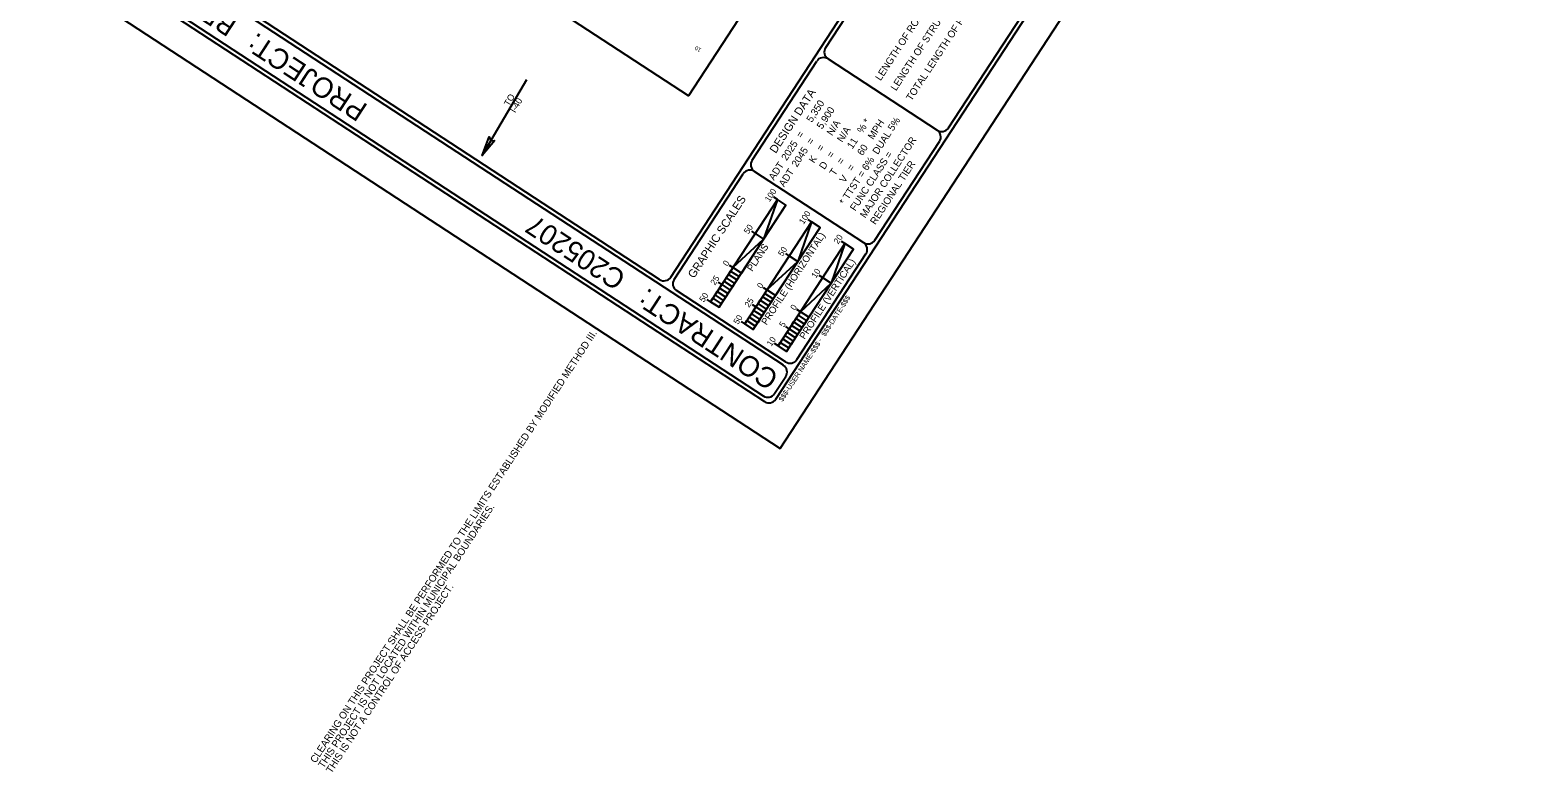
# Model space of a CAD drawing. Extents: x 1190029 to 2382315, y 163128 to 334830.
# Drawn here: x 2378613 to 2382315, y 329705 to 331527 of the extents above; entities that cross this region are included whole.
import ezdxf

# ---------------------------------------------------------------- set-up
doc = ezdxf.new("R2010")
doc.units = 0
for name, color, linetype in [('Exist Property Line', 7, 'Continuous'), ('Exist Utilities Telephone UG FO SUE LOS B Text', 7, 'Continuous'), ('Prop ROW Station Offsets', 7, 'Continuous'), ('Scratch_Level_4', 7, 'Continuous'), ('Sheet Block Title CELL', 7, 'Continuous'), ('Sheet_Plan_CELL', 7, 'Continuous'), ('z - Construction', 7, 'Continuous')]:
    doc.layers.add(name, color=color, linetype=linetype)

msp = doc.modelspace()

# ---------------------------------------------------------------- linework, layer by layer
at = {"layer": 'Exist Utilities Telephone UG FO SUE LOS B Text'}
for p, q in [((2380185.5, 330920.1), (2381876.3, 333506.5)), ((2380443.3, 330620.2), (2382199.8, 333307)), ((2380566, 331483.8), (2380981.8, 332119.9)), ((2380157.8, 330914.3), (2378801.9, 331800.8)), ((2380462, 330703.5), (2378796.4, 331792.4)), ((2378733.2, 331714.3), (2380415.6, 330614.4)), ((2378747.1, 331717.1), (2380412.8, 330628.2)), ((2380385.4, 331207.6), (2380544.1, 331450.3)), ((2380571.7, 331456.1), (2380839.6, 331281)), ((2380193.9, 330914.6), (2380363.5, 331174.1)), ((2380391.2, 331179.9), (2380659, 331004.8)), ((2380447.4, 331110.9), (2380283.2, 330859.8)), ((2380304.1, 330846.1), (2380468.3, 331097.2)), ((2380447.4, 331110.9), (2380439, 331116.4)), ((2380468.3, 331097.2), (2380447.4, 331110.9)), ((2380531.2, 331056.1), (2380522.9, 331061.6)), ((2380531.2, 331056.1), (2380367.1, 330805)), ((2380392.7, 331027.2), (2380384.3, 331032.7)), ((2380388, 330791.3), (2380552.2, 331042.4)), ((2380392.7, 331027.2), (2380413.6, 331013.5)), ((2380552.2, 331042.4), (2380531.2, 331056.1)), ((2380613.1, 331002.6), (2380448.9, 330751.5)), ((2380469.9, 330737.8), (2380634, 330988.9)), ((2380613.1, 331002.6), (2380604.7, 331008)), ((2380634, 330988.9), (2380613.1, 331002.6)), ((2380338, 330943.5), (2380329.6, 330949)), ((2380476.5, 330972.4), (2380468.2, 330977.9)), ((2380476.5, 330972.4), (2380497.4, 330958.7)), ((2380321.5, 330918.4), (2380342.4, 330904.7)), ((2380558.4, 330918.9), (2380550, 330924.3)), ((2380558.4, 330918.9), (2380579.3, 330905.2)), ((2380467.5, 330711.9), (2380199.7, 330887)), ((2380310.6, 330901.7), (2380302.2, 330907.1)), ((2380421.8, 330888.7), (2380413.4, 330894.2)), ((2380283.2, 330859.8), (2380274.9, 330865.3)), ((2380274.9, 330865.3), (2380274.9, 330865.3)), ((2380283.2, 330859.8), (2380304.1, 330846.1)), ((2380283.2, 330859.8), (2380283.2, 330859.8)), ((2380394.4, 330846.8), (2380386.1, 330852.3)), ((2380405.4, 330863.6), (2380426.3, 330849.9)), ((2380503.7, 330835.2), (2380495.3, 330840.6)), ((2380367.1, 330805), (2380358.7, 330810.5)), ((2380358.7, 330810.5), (2380358.7, 330810.5)), ((2380367.1, 330805), (2380388, 330791.3)), ((2380367.1, 330805), (2380367.1, 330805)), ((2380487.2, 330810.1), (2380508.2, 330796.4)), ((2380476.3, 330793.3), (2380467.9, 330798.8)), ((2380448.9, 330751.5), (2380440.6, 330756.9)), ((2380440.6, 330756.9), (2380440.6, 330756.9)), ((2380448.9, 330751.5), (2380469.9, 330737.8)), ((2380448.9, 330751.5), (2380448.9, 330751.5))]:
    msp.add_line(p, q, dxfattribs=at)
for points in [[(2380867.3, 331286.8), (2381283.2, 331922.9)], [(2380686.7, 331010.6), (2380845.4, 331253.3)], [(2380495.2, 330717.7), (2380664.8, 330977.1)], [(2380440.5, 330634), (2380467.8, 330675.8)]]:
    msp.add_lwpolyline(points, dxfattribs=at)
for points in [[(2380447.4, 331110.9), (2380413.6, 331013.5), (2380468.3, 331097.2)], [(2380531.2, 331056.1), (2380497.4, 330958.7), (2380552.2, 331042.4)], [(2380338, 330943.5), (2380413.6, 331013.5), (2380358.9, 330929.8)], [(2380613.1, 331002.6), (2380579.3, 330905.2), (2380634, 330988.9)], [(2380421.8, 330888.7), (2380497.4, 330958.7), (2380442.7, 330875)], [(2380316.1, 330910), (2380321.5, 330918.4), (2380342.4, 330904.7), (2380337, 330896.4)], [(2380327, 330926.8), (2380332.5, 330935.1), (2380353.4, 330921.5), (2380347.9, 330913.1)], [(2380294.2, 330876.6), (2380299.6, 330884.9), (2380320.6, 330871.2), (2380315.1, 330862.9)], [(2380305.1, 330893.3), (2380310.6, 330901.7), (2380331.5, 330888), (2380326, 330879.6)], [(2380410.8, 330872), (2380416.3, 330880.3), (2380437.3, 330866.6), (2380431.8, 330858.3)], [(2380503.7, 330835.2), (2380579.3, 330905.2), (2380524.6, 330821.5)], [(2380283.2, 330859.8), (2380288.7, 330868.2), (2380309.6, 330854.5), (2380304.1, 330846.1)], [(2380389, 330838.5), (2380394.4, 330846.8), (2380415.3, 330833.2), (2380409.9, 330824.8)], [(2380399.9, 330855.2), (2380405.4, 330863.6), (2380426.3, 330849.9), (2380420.8, 330841.5)], [(2380367.1, 330805), (2380372.5, 330813.4), (2380393.5, 330799.7), (2380388, 330791.3)], [(2380378, 330821.7), (2380383.5, 330830.1), (2380404.4, 330816.4), (2380399, 330808.1)], [(2380481.8, 330801.7), (2380487.2, 330810.1), (2380508.2, 330796.4), (2380502.7, 330788)], [(2380492.7, 330818.4), (2380498.2, 330826.8), (2380519.1, 330813.1), (2380513.6, 330804.7)], [(2380459.9, 330768.2), (2380465.4, 330776.6), (2380486.3, 330762.9), (2380480.8, 330754.5)], [(2380470.9, 330784.9), (2380476.3, 330793.3), (2380497.2, 330779.6), (2380491.8, 330771.3)], [(2380448.9, 330751.5), (2380454.4, 330759.8), (2380475.3, 330746.2), (2380469.9, 330737.8)]]:
    msp.add_lwpolyline(points, close=True, dxfattribs=at)
for centre, start, end in [((2380582.6, 331472.9), 146.8248, 236.8248), ((2380560.7, 331439.4), 56.8248, 146.8248), ((2380850.5, 331297.8), 236.8248, 326.8248), ((2380828.6, 331264.3), 326.8248, 56.8248), ((2380402.1, 331196.6), 146.8298, 236.8248), ((2380380.2, 331163.2), 56.8248, 146.8295), ((2380670, 331021.6), 236.8248, 326.8248), ((2380648.1, 330988.1), 326.8295, 56.8248), ((2380168.7, 330931.1), 236.8248, 326.8248), ((2380210.6, 330903.7), 146.8295, 236.8293), ((2380451, 330686.8), 326.8248, 56.8248), ((2380478.5, 330728.6), 236.8293, 326.8295), ((2380423.7, 330644.9), 236.8241, 326.8248), ((2380426.5, 330631.1), 236.8248, 326.8248)]:
    msp.add_arc(centre, 20, start, end, dxfattribs=at)
at = {"layer": 'Scratch_Level_4'}
msp.add_line((2379722.4, 331218.9), (2379832.1, 331405.9), dxfattribs=at)
at = {"layer": 'Sheet Block Title CELL'}
msp.add_lwpolyline([(2379753.8, 331256.1), (2379722.4, 331218.9), (2379739.5, 331264.9), (2379743.7, 331255.3)], close=True, dxfattribs=at)
at = {"layer": 'Sheet_Plan_CELL'}
msp.add_line((2380454, 330499.6), (2380454, 330499.6), dxfattribs=at)
msp.add_lwpolyline([(2379678.4, 331725.7), (2380382.5, 332802.6), (2380871.9, 332349.2), (2380229.4, 331365.5)], close=True, dxfattribs=at)
at = {"layer": 'z - Construction'}
for p, q in [((2380454, 330499.6), (2382314.5, 333345.4)), ((2378612.6, 331703.5), (2380454, 330499.6))]:
    msp.add_line(p, q, dxfattribs=at)

# ---------------------------------------------------------------- texts
at = {"layer": 'Exist Property Line'}
msp.add_text('10', height=10, rotation=149.6068, dxfattribs=at).set_placement((2380261.4, 331480.7))
at = {"layer": 'Exist Utilities Telephone UG FO SUE LOS B Text'}
for s, height, rotation, p in [('BR-0174 ', 50, 146.8248, (2379125.3, 331550.2)), ('       PROJECT:', 50, 146.8248, (2379553.1, 331270.5)), ('DESIGN DATA', 19.999, 56.8248, (2380443.4, 331222.6)), ('GRAPHIC SCALES', 19.999, 56.8248, (2380242.8, 330915.7)), (' C205207  ', 50, 146.8248, (2380094.4, 330916.7)), ('PROFILE (HORIZONTAL)', 16.999, 56.8248, (2380420.8, 330801)), ('PLANS', 17, 56.8248, (2380385.8, 330932.6)), ('0', 15, 56.8248, (2380324.6, 330945.6)), ('PROFILE (VERTICAL)', 16.999, 56.8248, (2380514.3, 330765.9)), ('CONTRACT:', 50, 146.8248, (2380453.8, 330681.7)), ('0', 15, 56.8248, (2380408.5, 330890.8)), ('0', 15, 56.8248, (2380490.4, 330837.3))]:
    msp.add_text(s, height=height, rotation=rotation, dxfattribs=at).set_placement(p)
at = {"layer": 'Prop ROW Station Offsets'}
for s, p in [('$$$-DATE-$$$', (2380564.6, 330773.6)), ('-', (2380554.8, 330760.4)), ('$$$-USER NAME-$$$', (2380459.8, 330612.9))]:
    msp.add_text(s, height=12.5, rotation=56.8248, dxfattribs=at).set_placement(p)
at = {"layer": 'Sheet_Plan_CELL'}
for s, height, rotation, p in [('LENGTH OF ROADWAY PROJECT BR-0174 = 0.335 MILES', 17.5, 56.8248, (2380700.8, 331401.1)), ('LENGTH OF STRUCTURE PROJECT BR-0174 = 0.029 MILES', 17.5, 56.8248, (2380738.7, 331376.3)), ('TOTAL LENGTH OF PROJECT BR-0174 = 0.364 MILES', 17.5, 56.8248, (2380776.7, 331351.5)), ('TO', 16, 59.607, (2379788.7, 331338.6)), ('I-40', 16, 59.607, (2379803.5, 331322.4)), ('5,350    ', 17.5, 56.8248, (2380531.8, 331298.7)), ('5,900    ', 17.5, 56.8248, (2380557, 331282.2)), ('N/A', 17.5, 56.8248, (2380581.8, 331266)), ('N/A', 17.5, 56.8248, (2380606.7, 331249.7)), ('% *', 17.5, 56.8248, (2380656.2, 331271.8)), ('MPH', 17.5, 56.8248, (2380682.5, 331256.6)), ('DUAL 5%', 17.5, 56.8248, (2380693.9, 331219.9)), ('2025', 17.5, 56.8248, (2380470.1, 331204.7)), ('=', 17.5, 56.8248, (2380506.6, 331260.2)), ('=', 17.5, 56.8248, (2380531.7, 331243.8)), ('=', 17.5, 56.8248, (2380556.6, 331227.6)), ('11', 17.5, 56.8248, (2380631.5, 331233.5)), ('60', 17.5, 56.8248, (2380656.4, 331217.2)), ('MAJOR COLLECTOR', 17.5, 56.8248, (2380663.1, 331063.8)), ('2045', 17.5, 56.8248, (2380495.3, 331188.7)), ('K', 17.5, 56.8248, (2380537.6, 331198.6)), ('=', 17.5, 56.8248, (2380581.7, 331211.1)), ('=', 17.5, 56.8248, (2380606.1, 331195.2)), ('* TTST = 6%', 17.5, 56.8248, (2380612.9, 331095.9)), ('FUNC CLASS =', 17.5, 56.8248, (2380638.7, 331081)), ('ADT', 17.5, 56.8248, (2380438.9, 331156.5)), ('ADT', 17.5, 56.8248, (2380463.8, 331140.2)), ('D', 17.5, 56.8248, (2380563, 331183)), ('T', 17.5, 56.8248, (2380588.7, 331167.7)), ('V', 17.5, 56.8248, (2380612.8, 331150.3)), ('=', 17.5, 56.8248, (2380631.2, 331178.8)), ('REGIONAL TIER', 17.5, 56.8248, (2380688.1, 331047.5)), ('100', 15, 56.8248, (2380427.8, 331103.4)), ('100', 15, 56.8248, (2380511.7, 331048.6)), ('50', 15, 56.8248, (2380376.3, 331024.6)), ('20', 15, 56.8248, (2380596.7, 331000)), ('50', 15, 56.8248, (2380460.1, 330969.8)), ('25', 15, 56.8248, (2380294.1, 330899)), ('10', 15, 56.8248, (2380542, 330916.3)), ('50', 15, 56.8248, (2380266.8, 330857.2)), ('25', 15, 56.8248, (2380378, 330844.2)), ('50', 15, 56.8248, (2380350.7, 330802.4)), ('5', 15, 56.8248, (2380463.1, 330795.5)), ('CLEARING ON THIS PROJECT SHALL BE PERFORMED TO THE LIMITS ESTABLISHED BY MODIFIED METHOD III.', 17.666, 56.8248, (2379313.6, 329725.2)), ('10', 15, 56.8248, (2380432.6, 330748.9)), ('THIS PROJECT IS NOT LOCATED WITHIN MUNICIPAL BOUNDARIES.', 17.666, 56.8248, (2379333, 329712.5)), ('THIS IS NOT A CONTROL OF ACCESS PROJECT.', 17.666, 56.8248, (2379352.4, 329699.9))]:
    msp.add_text(s, height=height, rotation=rotation, dxfattribs=at).set_placement(p)

doc.saveas('drawing.dxf')
